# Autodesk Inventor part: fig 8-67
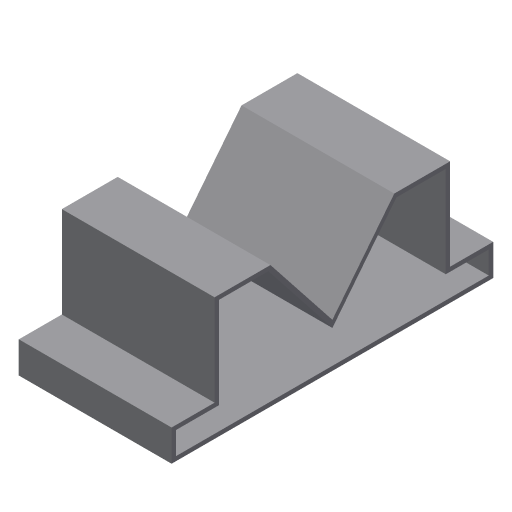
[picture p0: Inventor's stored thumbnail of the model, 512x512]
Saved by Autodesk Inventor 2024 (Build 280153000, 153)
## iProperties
Shininess: 77.0
Length Units: 11269
Angle Units: 11279
Time Units: 11290
Mass Units: 11283
Length Display Precision: 3
Angle Display Precision: 2
Created: 2002-01
Part Number: fig 8-67
Document SubType Name: Modeling
Designer: ***
Density: 1 g/cm^3
Material: Generic
Appearance: Default
Density: 0.0
Volumn: 0.0
Area: 0.0
PropertySet Name: Model Information
Control State: 0
Master: False
Checked Out: False
Author: ***
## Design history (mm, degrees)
sketch "Sketch2"
  geometry: L1 (0, 0)-(-14.184, 17.961); L2 (-14.184, 17.961)-(-26.987, 17.961); L3 (-26.987, 17.961)-(-26.987, -2.947); L4 (-26.987, -2.947)-(-36.842, -2.947); L5 (-36.842, -2.947)-(-36.842, -10.132); L6 (26.987, 17.961)-(26.987, -2.947); L7 (14.184, 17.961)-(26.987, 17.961); L8 (26.987, -2.947)-(36.842, -2.947); L9 (36.842, -10.132)-(-36.842, -10.132); L10 (36.842, -2.947)-(36.842, -10.132); L11 (0, 0)-(14.184, 17.961)
  constraints: 22 end point, 2 horizontal, 2 parallel, 1 perpendicular
extrude "Extrusion1" new body sketch "Sketch2" distance "d0" = 35; taper "d1" = 0 deg
shell "Shell3" dims "d13" = 1
body "Solid1"
node "Sketch1"
